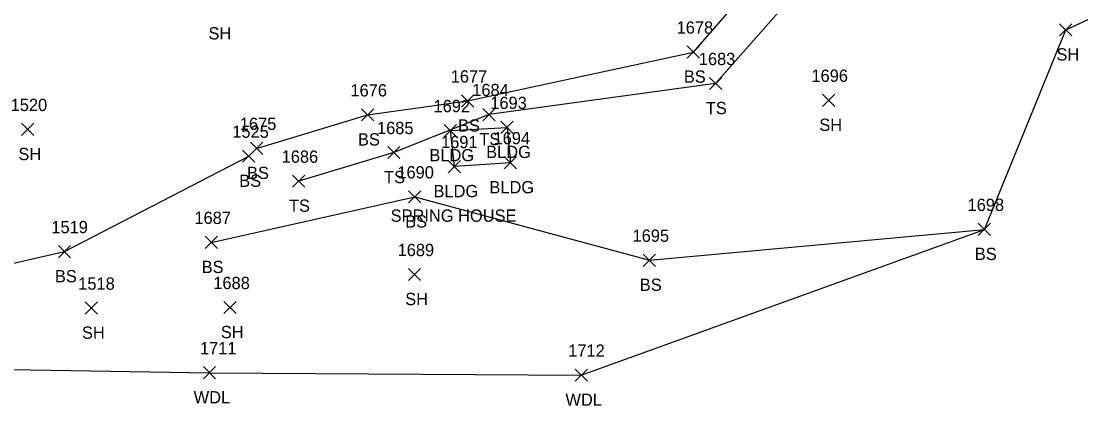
# Model space of a CAD drawing. Extents: x 1633660 to 1636532, y 388643 to 392631.
# Drawn here: x 1634224 to 1634396.6, y 388734.8 to 388797.6 of the extents above; entities that cross this region are included whole.
import ezdxf

# ---------------------------------------------------------------- set-up
doc = ezdxf.new("R2010")
doc.units = 0
for name, color, linetype in [('L_A', 7, 'Continuous'), ('L_C', 7, 'Continuous'), ('L_I', 7, 'Continuous'), ('L_TIC', 7, 'Continuous'), ('LAWA', 7, 'Continuous'), ('LBC', 7, 'Continuous'), ('LELB', 7, 'Continuous'), ('LSOGP', 7, 'Continuous')]:
    doc.layers.add(name, color=color, linetype=linetype)

msp = doc.modelspace()

# ---------------------------------------------------------------- linework, layer by layer
at = {"layer": 'L_TIC'}
for points in [[(1634393.19, 388795.15), (1634395.19, 388797.15)], [(1634395.19, 388795.15), (1634393.19, 388797.15)], [(1634332.52, 388791.53), (1634334.52, 388793.53)], [(1634334.52, 388791.53), (1634332.52, 388793.53)], [(1634336.14, 388786.4), (1634338.14, 388788.4)], [(1634338.14, 388786.4), (1634336.14, 388788.4)], [(1634295.72, 388783.56), (1634297.72, 388785.56)], [(1634297.72, 388783.56), (1634295.72, 388785.56)], [(1634354.54, 388783.67), (1634356.54, 388785.67)], [(1634356.54, 388783.67), (1634354.54, 388785.67)], [(1634279.42, 388781.29), (1634281.42, 388783.29)], [(1634281.42, 388781.29), (1634279.42, 388783.29)], [(1634299.22, 388781.34), (1634301.22, 388783.34)], [(1634301.22, 388781.34), (1634299.22, 388783.34)], [(1634302.16, 388779.25), (1634304.16, 388781.25)], [(1634304.16, 388779.25), (1634302.16, 388781.25)], [(1634224.05, 388778.91), (1634226.05, 388780.91)], [(1634226.05, 388778.91), (1634224.05, 388780.91)], [(1634292.91, 388778.72), (1634294.91, 388780.72)], [(1634294.91, 388778.72), (1634292.91, 388780.72)], [(1634261.35, 388775.83), (1634263.35, 388777.83)], [(1634263.35, 388775.83), (1634261.35, 388777.83)], [(1634260.07, 388774.55), (1634262.07, 388776.55)], [(1634262.07, 388774.55), (1634260.07, 388776.55)], [(1634283.7, 388775.15), (1634285.7, 388777.15)], [(1634285.7, 388775.15), (1634283.7, 388777.15)], [(1634293.58, 388772.86), (1634295.58, 388774.86)], [(1634295.58, 388772.86), (1634293.58, 388774.86)], [(1634302.69, 388773.49), (1634304.69, 388775.49)], [(1634304.69, 388773.49), (1634302.69, 388775.49)], [(1634268.21, 388770.48), (1634270.21, 388772.48)], [(1634270.21, 388770.48), (1634268.21, 388772.48)], [(1634287.11, 388767.92), (1634289.11, 388769.92)], [(1634289.11, 388767.92), (1634287.11, 388769.92)], [(1634379.93, 388762.62), (1634381.93, 388764.62)], [(1634381.93, 388762.62), (1634379.93, 388764.62)], [(1634253.95, 388760.5), (1634255.95, 388762.5)], [(1634255.95, 388760.5), (1634253.95, 388762.5)], [(1634230.04, 388758.99), (1634232.04, 388760.99)], [(1634232.04, 388758.99), (1634230.04, 388760.99)], [(1634325.34, 388757.59), (1634327.34, 388759.59)], [(1634327.34, 388757.59), (1634325.34, 388759.59)], [(1634287.07, 388755.26), (1634289.07, 388757.26)], [(1634289.07, 388755.26), (1634287.07, 388757.26)], [(1634234.4, 388749.78), (1634236.4, 388751.78)], [(1634236.4, 388749.78), (1634234.4, 388751.78)], [(1634257.03, 388749.88), (1634259.03, 388751.88)], [(1634259.03, 388749.88), (1634257.03, 388751.88)], [(1634253.67, 388739.24), (1634255.67, 388741.24)], [(1634255.67, 388739.24), (1634253.67, 388741.24)], [(1634314.25, 388738.85), (1634316.25, 388740.85)], [(1634316.25, 388738.85), (1634314.25, 388740.85)]]:
    msp.add_lwpolyline(points, dxfattribs=at)
at = {"layer": 'LAWA'}
msp.add_lwpolyline([(1634218.98, 388740.85), (1634254.67, 388740.24), (1634315.25, 388739.85)], dxfattribs=at)
at = {"layer": 'LBC'}
for points in [[(1634294.58, 388773.86), (1634293.91, 388779.72), (1634303.16, 388780.25), (1634303.69, 388774.49)], [(1634303.69, 388774.49), (1634294.58, 388773.86)]]:
    msp.add_lwpolyline(points, dxfattribs=at)
at = {"layer": 'LELB'}
for points in [[(1634262.35, 388776.83), (1634280.42, 388782.29), (1634296.72, 388784.56), (1634333.52, 388792.53), (1634353.08, 388815.01), (1634360.72, 388835.15)], [(1634363.3, 388829.26), (1634356.87, 388809.82), (1634337.14, 388787.4), (1634300.22, 388782.34), (1634284.7, 388776.15), (1634269.21, 388771.48)], [(1634139.55, 388754.21), (1634148.69, 388747.39), (1634177.92, 388748.25), (1634206.1, 388754.31), (1634231.04, 388759.99), (1634261.07, 388775.55)], [(1634254.95, 388761.5), (1634288.11, 388768.92), (1634326.34, 388758.59), (1634380.93, 388763.62)]]:
    msp.add_lwpolyline(points, dxfattribs=at)
at = {"layer": 'LSOGP'}
msp.add_lwpolyline([(1634218.98, 388740.85), (1634254.67, 388740.24), (1634315.25, 388739.85), (1634380.93, 388763.62), (1634394.19, 388796.15), (1634428.1, 388811.92), (1634452.29, 388827.49), (1634483.59, 388839.11), (1634515.33, 388848.44), (1634546.28, 388863.72), (1634572.45, 388876.23), (1634604.94, 388890.27), (1634644.29, 388911.66), (1634697.95, 388942.99), (1634729.71, 388982.06), (1634750.63, 388992.22), (1634777.03, 389014.48), (1634810.97, 389037.99), (1634811.65, 389038.97), (1634835.21, 389072.38), (1634837.85, 389085.95), (1634849.33, 389112.53), (1634851.42, 389137.05)], dxfattribs=at)

# ---------------------------------------------------------------- texts
at = {"layer": 'L_A'}
for s, p in [('SH', (1634254.51, 388794.58)), ('SH', (1634392.68, 388791.15)), ('BS', (1634331.96, 388787.53)), ('TS', (1634335.54, 388782.4)), ('BS', (1634295.16, 388779.56)), ('SH', (1634354.03, 388779.67)), ('BS', (1634278.86, 388777.29)), ('TS', (1634298.63, 388777.34)), ('SH', (1634223.53, 388774.91)), ('BLDG', (1634290.5, 388774.72)), ('BLDG', (1634299.75, 388775.25)), ('BS', (1634259.51, 388770.55)), ('BS', (1634260.79, 388771.83)), ('TS', (1634283.11, 388771.15)), ('BLDG', (1634291.17, 388768.86)), ('BLDG', (1634300.28, 388769.49)), ('TS', (1634267.62, 388766.48)), ('BS', (1634286.55, 388763.92)), ('BS', (1634379.37, 388758.62)), ('BS', (1634229.48, 388754.99)), ('BS', (1634253.39, 388756.5)), ('BS', (1634324.78, 388753.59)), ('SH', (1634286.56, 388751.26)), ('SH', (1634233.89, 388745.78)), ('SH', (1634256.52, 388745.88)), ('WDL', (1634252.09, 388735.24)), ('WDL', (1634312.67, 388734.85))]:
    msp.add_text(s, height=2, dxfattribs=at).set_placement(p)
at = {"layer": 'L_C'}
msp.add_text('SPRING HOUSE', height=2, dxfattribs=at).set_placement((1634284.18, 388764.86))
at = {"layer": 'L_I'}
for s, p in [('1678', (1634330.78, 388795.53)), ('1683', (1634334.4, 388790.4)), ('1696', (1634352.75, 388787.67)), ('1677', (1634293.98, 388787.56)), ('1676', (1634277.63, 388785.29)), ('1684', (1634297.48, 388785.34)), ('1520', (1634222.27, 388782.91)), ('1692', (1634291.17, 388782.72)), ('1693', (1634300.42, 388783.25)), ('1675', (1634259.61, 388779.83)), ('1685', (1634281.96, 388779.15)), ('1525', (1634258.38, 388778.55)), ('1694', (1634300.95, 388777.49)), ('1691', (1634292.4, 388776.86)), ('1686', (1634266.42, 388774.48)), ('1690', (1634285.28, 388771.92)), ('1698', (1634378.19, 388766.62)), ('1687', (1634252.21, 388764.5)), ('1519', (1634228.9, 388762.99)), ('1695', (1634323.6, 388761.59)), ('1689', (1634285.32, 388759.26)), ('1518', (1634233.28, 388753.78)), ('1688', (1634255.29, 388753.88)), ('1711', (1634253.11, 388743.24)), ('1712', (1634313.12, 388742.85))]:
    msp.add_text(s, height=2, dxfattribs=at).set_placement(p)

doc.saveas('drawing.dxf')
